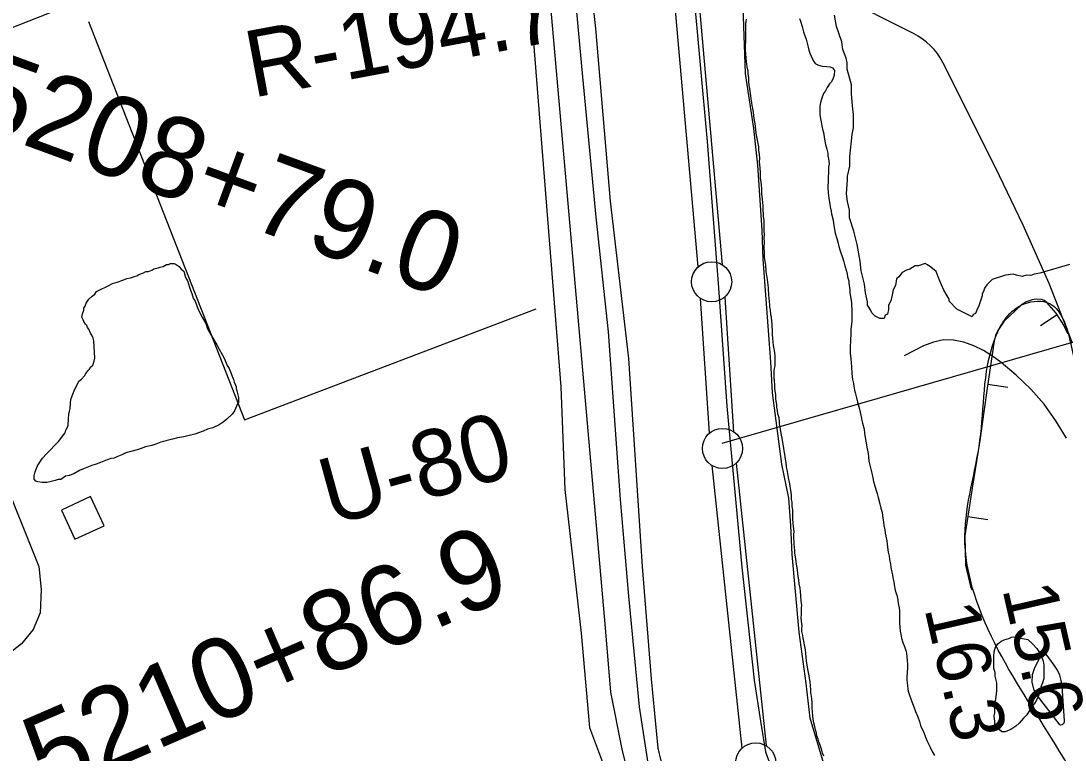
# Model space of a CAD drawing. Extents: x 3324125 to 3362000, y 600753 to 626151.
# Drawn here: x 3331428 to 3332729, y 615545 to 616457 of the extents above; entities that cross this region are included whole.
import ezdxf

# ---------------------------------------------------------------- set-up
doc = ezdxf.new("R2010")
doc.units = 0
for name, color, linetype in [('V-BLDG-OTLN', 7, 'Continuous'), ('V-BORW-LINE', 7, 'Continuous'), ('V-FLOD-BASE', 7, 'Continuous'), ('V-LEVE-TOET', 7, 'Continuous'), ('V-RIVR-RANG', 7, 'Continuous'), ('V-RIVR-RANG-IDEN', 7, 'Continuous'), ('V-ROAD-CNTR', 7, 'Continuous'), ('V-SITE-VEGE', 7, 'Continuous'), ('V-SURV-IDEN', 7, 'Continuous'), ('V-SURV-LINE', 7, 'Continuous'), ('V-TOPO-MAJR', 7, 'Continuous'), ('V-TOPO-MINR', 7, 'Continuous'), ('V-TOPO-SHOR', 7, 'Continuous')]:
    doc.layers.add(name, color=color, linetype=linetype)

msp = doc.modelspace()

# ---------------------------------------------------------------- linework, layer by layer
at = {"layer": 'V-BLDG-OTLN'}
msp.add_lwpolyline([(3331478.4, 615847.9), (3331495.3, 615811.6), (3331531.6, 615828.4), (3331514.7, 615864.7)], close=True, dxfattribs=at)
at = {"layer": 'V-BORW-LINE'}
for p, q in [((3332718.9, 616090.9), (3332697.8, 616077.5)), ((3332632.4, 616004.7), (3332657.2, 616001.1)), ((3332607.5, 615839.9), (3332632.2, 615836.1))]:
    msp.add_line(p, q, dxfattribs=at)
msp.add_lwpolyline([(3332731.9, 616067.4), (3332727.1, 616078.1), (3332717.6, 616093.1), (3332705.8, 616106.6), (3332702.6, 616108.9), (3332699.2, 616110.2), (3332692.8, 616110.7), (3332687.7, 616109.9), (3332680.3, 616107.2), (3332674, 616103), (3332652.7, 616083.1), (3332644.7, 616071.7), (3332642, 616065.5), (3332640.3, 616058.8), (3332631.3, 615996.6), (3332622.6, 615934.4), (3332612.9, 615875), (3332603.8, 615815.7), (3332604.4, 615779.4), (3332610.8, 615752.5), (3332612.4, 615748.3)], dxfattribs=at)
msp.add_spline([(3332917.4, 615371.8), (3332899, 615439.4), (3332887.3, 615494.3), (3332880.8, 615523.3), (3332845.9, 615674.6), (3332824, 615722.5), (3332777.6, 615836.6), (3332752.4, 615941.7), (3332736.3, 616052.4), (3332705.8, 616106.6), (3332674, 616103), (3332640.3, 616058.8), (3332622.6, 615934.4), (3332603.8, 615815.7), (3332645.4, 615673.5), (3332721.4, 615548), (3332760.5, 615451.5), (3332755.7, 615377.8), (3332775.8, 615229.9), (3332813.7, 615165), (3332893.3, 615037.2), (3332934.5, 614958.4), (3332934.6, 614916.2), (3332988.5, 614783.9), (3333008.6, 614752.7), (3333075.6, 614714.2), (3333096.8, 614723.6), (3333115.8, 614749.8), (3333132, 614783.4), (3333134.7, 614840.7), (3333127.6, 614881.8), (3333098, 614931.1), (3333018.3, 615080.4), (3332968.6, 615208.8), (3332941.7, 615292.2), (3332917.4, 615371.8)], degree=3, dxfattribs=at)
at = {"layer": 'V-FLOD-BASE'}
msp.add_lwpolyline([(3332227.4, 616947.5), (3332230.4, 616875.1), (3332240.2, 616761.9), (3332252.8, 616641.6), (3332265.3, 616498.5), (3332282.8, 616307), (3332296.8, 616124.8), (3332307.5, 615977.1), (3332326, 615776.8), (3332341.5, 615636.1), (3332349.3, 615584.7), (3332355.5, 615546.7), (3332369.2, 615509.3), (3332410.1, 615416.8), (3332454.9, 615312.6), (3332517, 615173.9)], dxfattribs=at)
at = {"layer": 'V-LEVE-TOET'}
for points in [[(3332098.6, 616972.3), (3332097, 616912.8), (3332109.7, 616793), (3332125.4, 616612.6), (3332143.6, 616447.9), (3332162.1, 616232.5), (3332184.7, 616036.8), (3332201.7, 615777.6), (3332213.1, 615637.5), (3332221.3, 615551.1), (3332240, 615472.2), (3332264.7, 615412.5), (3332328.7, 615293.6), (3332371.9, 615197.6)], [(3332428.3, 615531.7), (3332411.2, 615588.4), (3332406.2, 615631.6), (3332397.3, 615695.8), (3332388.5, 615792.6), (3332387.1, 615828.8), (3332384.4, 615862.8), (3332375.9, 615904.9), (3332364.3, 615994), (3332362, 616032.7), (3332352.6, 616160.4), (3332351.5, 616196.6), (3332346.1, 616277.4), (3332340.9, 616323), (3332330.7, 616391.5), (3332327.8, 616474.5), (3332325.5, 616507.5), (3332317.3, 616593.3), (3332302.9, 616718.9), (3332296.5, 616811.1), (3332286, 616894.6), (3332282.9, 616965.2)]]:
    msp.add_lwpolyline(points, dxfattribs=at)
at = {"layer": 'V-RIVR-RANG'}
msp.add_line((3332301.4, 615931.2), (3333589, 616302.4), dxfattribs=at)
at = {"layer": 'V-ROAD-CNTR'}
for points in [[(3332050.3, 616945.8), (3332056, 616867), (3332083.1, 616527.3), (3332155.9, 615701.2), (3332162.6, 615620.8), (3332176.4, 615550.1), (3332191.1, 615490.1), (3332204, 615447.5), (3332252.4, 615333.1), (3332828.6, 614063.2)], [(3332062.8, 616703.3), (3331299.1, 616402.5), (3331283.7, 616393.5), (3331269.2, 616382.1), (3331260.5, 616370.6), (3331252.7, 616347.9), (3331246.8, 616320), (3331249.3, 616296.2), (3331258.3, 616256.3), (3331450.3, 615777.5), (3331453.2, 615748.7), (3331451.9, 615720), (3331443.3, 615699.2), (3331428.9, 615681.4), (3331411.3, 615667.7), (3331394.3, 615658.1), (3330239.3, 615193.5), (3328629.8, 614542.4), (3328220.6, 614377)]]:
    msp.add_lwpolyline(points, dxfattribs=at)
at = {"layer": 'V-SITE-VEGE'}
for points in [[(3332734.1, 616153.6), (3332697, 616142.9), (3332690.1, 616141.6), (3332686, 616140.2), (3332680.5, 616140.3), (3332675, 616138.9), (3332668.1, 616140.4), (3332664, 616141.8), (3332654.4, 616140.4), (3332637.9, 616135.1), (3332631, 616128.3), (3332628.3, 616124.2), (3332626.9, 616120), (3332625.5, 616117.3), (3332625.4, 616114.6), (3332621.3, 616102.3), (3332618.5, 616096.8), (3332617.1, 616092.7), (3332614.3, 616091.3), (3332612.9, 616088.6), (3332602, 616094.1), (3332593.8, 616098.3), (3332584.3, 616108), (3332584.3, 616110.7), (3332581.6, 616114.9), (3332577.5, 616121.7), (3332574.8, 616128.6), (3332570.7, 616138.2), (3332568, 616145.1), (3332561.2, 616150.6), (3332557.1, 616153.4), (3332554.4, 616154.8), (3332546.1, 616152.1), (3332542, 616152.1), (3332535.1, 616148.1), (3332531, 616146.7), (3332525.5, 616144), (3332521.4, 616138.6), (3332518.6, 616135.8), (3332517.2, 616127.6), (3332514.4, 616122.1), (3332513, 616113.9), (3332511.6, 616108.4), (3332508.8, 616103), (3332508.7, 616097.5), (3332507.3, 616092), (3332504.6, 616090.7), (3332503.2, 616086.6), (3332500.4, 616086.6), (3332497.7, 616086.6), (3332492.2, 616089.4), (3332488.1, 616093.5), (3332486.8, 616096.3), (3332484.1, 616100.4), (3332482.7, 616103.1), (3332482.7, 616107.3), (3332480.1, 616118.3), (3332478.8, 616129.2), (3332474.8, 616145.7), (3332473.5, 616158.1), (3332469.5, 616178.7), (3332465.5, 616195.2), (3332460.1, 616211.7), (3332460.2, 616221.3), (3332457.5, 616232.2), (3332456.2, 616241.9), (3332457.7, 616259.7), (3332457.7, 616263.8), (3332460.5, 616276.1), (3332460.6, 616288.5), (3332463.5, 616315.9), (3332464.9, 616324.1), (3332465, 616340.6), (3332463.7, 616351.5), (3332462.5, 616366.6), (3332462.5, 616377.6), (3332457.2, 616396.9), (3332457.2, 616405.1), (3332455.9, 616410.6), (3332451.9, 616421.6), (3332450.5, 616431.2), (3332443.8, 616450.4), (3332441.2, 616464.2)], [(3331583.2, 615926.8), (3331577.6, 615924.5), (3331572.8, 615922.9), (3331564.9, 615920.6), (3331558.5, 615919), (3331553.7, 615916.7), (3331547.3, 615914.3), (3331544.1, 615912.7), (3331540.1, 615912), (3331535.3, 615910.4), (3331527.3, 615907.3), (3331521.7, 615904.9), (3331516.2, 615903.3), (3331505.8, 615899.4), (3331501, 615897.1), (3331493.8, 615893.1), (3331488.2, 615890.8), (3331483.4, 615890), (3331477.8, 615886.1), (3331474.6, 615886.1), (3331470.6, 615884.5), (3331464.2, 615883), (3331460.3, 615882.2), (3331454.7, 615882.2), (3331449.1, 615883.1), (3331446.7, 615883.9), (3331444.4, 615886.3), (3331444.4, 615890.3), (3331445.2, 615894.3), (3331448.4, 615902.2), (3331451.7, 615907.7), (3331454.9, 615912.5), (3331459.7, 615918.1), (3331474.9, 615933.1), (3331481.4, 615941.8), (3331483, 615944.2), (3331483.8, 615947.4), (3331486.2, 615951.3), (3331487, 615953.7), (3331487.1, 615961.7), (3331487.9, 615967.3), (3331488.7, 615971.2), (3331489.5, 615974.4), (3331489.6, 615981.6), (3331490.4, 615985.6), (3331492, 615990.3), (3331495.3, 615998.3), (3331498.5, 616004.6), (3331500.1, 616008.6), (3331503.3, 616011), (3331507.3, 616014.9), (3331508.9, 616018.1), (3331511.3, 616021.3), (3331512.9, 616022.9), (3331514.6, 616026), (3331517.8, 616028.4), (3331519.4, 616033.2), (3331520.2, 616037.1), (3331518.8, 616058.7), (3331518, 616061.8), (3331516.4, 616065.8), (3331514.8, 616068.2), (3331512.5, 616073), (3331510.9, 616075.4), (3331510.1, 616077.8), (3331508.5, 616079.4), (3331506.2, 616082.6), (3331505.4, 616085), (3331503.8, 616088.2), (3331504.6, 616092.2), (3331506.3, 616097), (3331506.3, 616099.4), (3331507.9, 616101.7), (3331509.5, 616105.7), (3331512.7, 616110.5), (3331516.7, 616114.4), (3331519.9, 616116.8), (3331522.3, 616120), (3331527.9, 616123.1), (3331533.5, 616125.5), (3331537.5, 616127.8), (3331542.3, 616130.2), (3331547.9, 616131.7), (3331555.1, 616134.1), (3331559.9, 616136.5), (3331564.7, 616137.2), (3331569.4, 616138.8), (3331572.6, 616139.6), (3331575, 616141.1), (3331580.6, 616143.5), (3331583.8, 616145.1), (3331587, 616145), (3331591, 616146.6), (3331593.4, 616148.2), (3331599, 616149.7), (3331601.4, 616150.5), (3331605.4, 616151.3), (3331609.4, 616153.7), (3331611.8, 616153.6), (3331614.2, 616155.2), (3331618.9, 616155.2)], [(3331618.9, 616155.2), (3331621.3, 616153.6), (3331625.3, 616151.2), (3331627.7, 616148), (3331630.8, 616145.6), (3331633.2, 616137.6), (3331635.5, 616133.6), (3331639.4, 616121.6), (3331641, 616117.6), (3331642.6, 616112), (3331644.9, 616108), (3331648.8, 616097.6), (3331653.6, 616088.1), (3331658.3, 616080.1), (3331660.6, 616073.7), (3331672.4, 616052.9), (3331674.8, 616048.1), (3331678.7, 616041.7), (3331681.1, 616036.9), (3331682.7, 616032.9), (3331685, 616028.1), (3331687.4, 616024.1), (3331692.9, 616010.5), (3331693.7, 616007.3), (3331696, 616001.8), (3331696, 615999.4), (3331696.8, 615996.2), (3331698.3, 615991.4), (3331699.1, 615988.2), (3331699.1, 615981.8), (3331697.5, 615979.4), (3331696.6, 615977.1), (3331694.2, 615971.5), (3331691, 615967.5), (3331684.6, 615961.2), (3331679.8, 615957.3), (3331675, 615954.1), (3331667, 615950.2), (3331660.6, 615948.6), (3331655, 615946.3), (3331644.6, 615942.3), (3331637.5, 615940.8), (3331631.1, 615939.2), (3331623.1, 615937.7), (3331616.7, 615936.2), (3331602.4, 615932.3), (3331596, 615929.9), (3331591.2, 615928.4), (3331583.2, 615926.8)]]:
    msp.add_lwpolyline(points, dxfattribs=at)
at = {"layer": 'V-SURV-LINE'}
for points in [[(3332271.7, 616150.7), (3332204.2, 616912.5)], [(3332234.1, 616915.1), (3332301.6, 616153.4)], [(3332285.6, 615943.6), (3332274.7, 616111.3)], [(3332304.7, 616113.2), (3332315.5, 615945.5)], [(3332326.3, 615551.2), (3332289, 615903.2)], [(3332318.9, 615906.3), (3332356.1, 615554.4)]]:
    msp.add_lwpolyline(points, dxfattribs=at)
for centre in [(3332288.4, 616132.2), (3332301.9, 615924.6), (3332343.3, 615532.9)]:
    msp.add_circle(centre, 25, dxfattribs=at)
at = {"layer": 'V-TOPO-MAJR'}
msp.add_lwpolyline([(3332738, 616055.9), (3332708.7, 616129.9), (3332676.5, 616202.7), (3332642.1, 616274.7), (3332576.3, 616405.6), (3332573.1, 616411.2), (3332569.5, 616416.6), (3332565.5, 616421.6), (3332561, 616426.3), (3332556.2, 616430.6), (3332551.1, 616434.6), (3332545.7, 616438.2), (3332540, 616441.4), (3332445.4, 616489.4), (3332444.4, 616489.8), (3332442.3, 616490.2), (3332438.9, 616489.9)], dxfattribs=at)
at = {"layer": 'V-TOPO-MINR'}
for points in [[(3332730.3, 615937.3), (3332717.3, 615959.1), (3332702.7, 615979.7), (3332685.9, 615998.4), (3332667.5, 616016), (3332649.1, 616031.6), (3332638.4, 616039.6), (3332627.1, 616046.7), (3332615, 616052.4), (3332602.5, 616057.2), (3332589.6, 616059.5), (3332577, 616059.9), (3332564.6, 616057.2), (3332552.4, 616052.6), (3332528.3, 616040)], [(3332700.5, 615669.6), (3332699.9, 615669.2), (3332699.4, 615668.5), (3332690.6, 615651.5), (3332687.8, 615642.4), (3332687.1, 615633.5), (3332689.4, 615624.8), (3332693.8, 615616.4), (3332721, 615581.4), (3332723.1, 615580.1), (3332725.5, 615580.6), (3332727.4, 615582.7), (3332727.8, 615583.9), (3332727.9, 615585.4), (3332725, 615628.3), (3332723.9, 615635.4), (3332722, 615642.1), (3332719, 615648.4), (3332715.2, 615654.5), (3332704.9, 615668.3), (3332703.6, 615669.4), (3332702, 615669.9), (3332700.5, 615669.6)]]:
    msp.add_lwpolyline(points, dxfattribs=at)
at = {"layer": 'V-TOPO-SHOR'}
for points in [[(3332079.8, 617015.2), (3332079.2, 616924), (3332083.6, 616853.8), (3332095.6, 616737.5), (3332102.8, 616629.9), (3332115.3, 616517.9), (3332127.6, 616387.6), (3332144.3, 616212.6), (3332159.4, 616070), (3332174.3, 615861.2), (3332184.7, 615740.4), (3332198.2, 615602.9), (3332211.5, 615516.4), (3332226.3, 615457), (3332245.5, 615405.9), (3332276.9, 615338.4), (3332310.8, 615281.2), (3332354.3, 615179.4)], [(3332049.3, 616645.5), (3332100.4, 616001.2), (3332105.5, 615873.4), (3332126, 615694.4), (3332136.2, 615576.8), (3332182.2, 615454.1), (3332264.1, 615239.3), (3332483.9, 614768.9), (3332673.1, 614344.5), (3332708.9, 614267.7)], [(3331512.4, 616456.3), (3331706.7, 615960.3), (3332069.7, 616098.4)], [(3332363.9, 616076.5), (3332363.6, 616079.7), (3332363.2, 616082.8), (3332362.8, 616088), (3332362, 616091.2), (3332361.7, 616097.2), (3332360.9, 616100.4), (3332360.9, 616104), (3332360.6, 616107.1), (3332360.2, 616112.3), (3332359.8, 616115.5), (3332359.1, 616124.3), (3332358.7, 616128.3), (3332358, 616135), (3332357.2, 616140.2), (3332356.4, 616145), (3332355.7, 616153), (3332354.9, 616157.8), (3332354.1, 616162.5), (3332354.2, 616169.3), (3332353.8, 616174.1), (3332354.3, 616181.7), (3332353.9, 616186.4), (3332354.3, 616191.2), (3332354, 616195.6), (3332354, 616201.2), (3332353.6, 616205.2), (3332353.6, 616208.4), (3332352.9, 616213.9), (3332352.9, 616217.5), (3332352.5, 616221.1), (3332352.6, 616226.7), (3332352.2, 616231.1), (3332351.8, 616235), (3332351.1, 616242.2), (3332351.1, 616247.4), (3332350.4, 616253.4), (3332349.2, 616262.1), (3332349.3, 616268.1), (3332348.9, 616274.1), (3332348.1, 616281.7), (3332348.2, 616286.4), (3332347.8, 616290.8), (3332347, 616296.4), (3332347.1, 616300.4), (3332345.9, 616306.4), (3332345.1, 616310.8), (3332344.4, 616314.8), (3332343.6, 616321.1), (3332342.9, 616325.5), (3332342.5, 616329.5), (3332341.3, 616335.5), (3332341, 616339.5), (3332340.6, 616343.1), (3332339.8, 616348.6), (3332339, 616351.8), (3332338.3, 616355), (3332337.5, 616360.6), (3332337.1, 616363.8), (3332336, 616373), (3332335.2, 616376.9), (3332334.8, 616381.3), (3332334.5, 616386.9), (3332333.7, 616390.9), (3332333.7, 616394.5), (3332332.6, 616400.1), (3332332.2, 616403.2), (3332331.8, 616406.4), (3332331.5, 616410.8), (3332331.1, 616416.4), (3332330.7, 616421.2), (3332330.7, 616424.8), (3332330.8, 616433.1), (3332330.8, 616437.5), (3332330.9, 616443.9), (3332330.9, 616448.7), (3332330.9, 616453.4), (3332331.8, 616459.4)], [(3332397.9, 616460.2), (3332399.1, 616457), (3332401, 616450.2), (3332401.8, 616447), (3332403, 616443.8), (3332404.1, 616439.8), (3332406.1, 616434.6), (3332407.2, 616429.4), (3332408.8, 616424.7), (3332409.6, 616420.7), (3332410.8, 616417.1), (3332412.3, 616413.5), (3332413.9, 616409.5), (3332415.5, 616406.7), (3332417.4, 616404.3), (3332421.4, 616401.9), (3332426.2, 616401), (3332431.4, 616400.6), (3332436.1, 616399.8), (3332438.9, 616398.6), (3332441.3, 616395.4), (3332440.8, 616389.8), (3332439.2, 616384.6), (3332437.2, 616381.1), (3332435.2, 616378.7), (3332432.4, 616374.3), (3332430, 616370), (3332427.9, 616366.8), (3332425.9, 616362.4), (3332424.3, 616357.2), (3332423.1, 616350.9), (3332423, 616347.7), (3332423, 616340.5), (3332423.8, 616335.3), (3332424.9, 616331.4), (3332425.7, 616326.6), (3332426.5, 616322.2), (3332427.6, 616318.2), (3332428.4, 616313), (3332429.2, 616307.4), (3332430.3, 616303.4), (3332431.9, 616297.5), (3332433, 616292.3), (3332433, 616289.1), (3332433.8, 616285.5), (3332434.6, 616279.1), (3332434.1, 616275.1), (3332434.1, 616268.4), (3332433.7, 616262.8), (3332433.6, 616258)], [(3332433.6, 616258), (3332433.2, 616250.1), (3332433.5, 616242.5), (3332434.7, 616233.3), (3332435.4, 616228.9), (3332436.2, 616225.7), (3332437.4, 616220.2), (3332437.7, 616217), (3332439.7, 616209), (3332440.1, 616205.4), (3332441.6, 616197.4), (3332442.4, 616193), (3332444.3, 616186.3), (3332445.5, 616181.5), (3332447, 616176.3), (3332448.6, 616170.7), (3332451.3, 616162.3), (3332452.9, 616157.1), (3332454.4, 616152.3), (3332456.4, 616145.6), (3332457.2, 616141.6), (3332457.5, 616138.4), (3332459.1, 616133.6), (3332459.1, 616130.4), (3332460.6, 616122), (3332460.6, 616118.5), (3332461.7, 616111.3), (3332462.5, 616106.1), (3332462.8, 616094.9), (3332462.8, 616089), (3332462.8, 616082.6), (3332461.9, 616073.4), (3332461.9, 616067.1), (3332461.4, 616059.9), (3332461, 616049.9), (3332460.9, 616043.2), (3332461.7, 616036.4), (3332462.4, 616026.4), (3332463.1, 616018.1), (3332463.9, 616010.5), (3332465, 616005.7), (3332465.4, 616002.1), (3332466.2, 615997.3), (3332467, 615994.2), (3332468.9, 615987.8), (3332470.1, 615982.2), (3332471.6, 615976.6), (3332472.4, 615973.4), (3332473.2, 615969.8), (3332474.7, 615963.8), (3332475.5, 615959.4), (3332476.3, 615955.9), (3332478.2, 615948.7), (3332478.6, 615943.5), (3332480.1, 615935.9), (3332480.9, 615931.5), (3332481.7, 615926.4), (3332483.2, 615918.4), (3332483.6, 615914), (3332484.3, 615908.8), (3332485.9, 615902), (3332487, 615897.2), (3332487.8, 615893.7), (3332489, 615888.1), (3332490.1, 615883.3), (3332491.3, 615879.3), (3332493.3, 615872.1), (3332494.4, 615868.5), (3332496, 615863.3), (3332497.9, 615855.8), (3332499.1, 615850.2), (3332500.6, 615845), (3332501.8, 615837.8), (3332502.6, 615833), (3332502.9, 615828.6), (3332504.1, 615823.1), (3332504.5, 615819.1), (3332505.2, 615815.5), (3332506.4, 615809.5), (3332506.8, 615805.5), (3332507.5, 615801.5), (3332508.3, 615795.2), (3332509.5, 615790.4), (3332509.8, 615786.4), (3332511, 615780.4), (3332511.4, 615776.4), (3332512.9, 615770.4), (3332513.7, 615767.2), (3332514.1, 615763.3), (3332515.2, 615758.5), (3332515.6, 615754.5), (3332517.1, 615748.1), (3332518.3, 615744.1), (3332519.5, 615740.5), (3332520.3, 615735.3), (3332520.6, 615731.3), (3332521.8, 615726.2), (3332522.2, 615722.2), (3332522.5, 615717.4), (3332522.5, 615712.2), (3332522.5, 615707.4)], [(3332411.6, 615628.5), (3332410.9, 615634.1), (3332410.1, 615638.1), (3332409.7, 615641.3), (3332408.6, 615647.6), (3332407.4, 615654.8), (3332406.7, 615660), (3332406.3, 615664), (3332405.5, 615669.6), (3332405.2, 615673.6), (3332404, 615679.9), (3332403.2, 615684.7), (3332402.5, 615688.3), (3332402.1, 615691.5), (3332400.9, 615696.7), (3332400.9, 615700.3), (3332401, 615703.8), (3332400.2, 615709.4), (3332399.8, 615713.8), (3332400.3, 615717.4), (3332400.3, 615722.6), (3332400.3, 615726.2), (3332400.7, 615729.3), (3332400, 615734.5), (3332399.6, 615740.9), (3332398.9, 615746.5), (3332398.5, 615750.5), (3332397.3, 615756), (3332397, 615760.8), (3332396.2, 615765.2), (3332395.8, 615768.8), (3332395.4, 615773.2), (3332395.1, 615776.4), (3332393.9, 615780.4), (3332393.5, 615783.9), (3332392.8, 615789.5), (3332392, 615794.3), (3332392, 615797.5), (3332391.3, 615805.9), (3332391.3, 615809), (3332390.9, 615812.6), (3332390.9, 615817.4), (3332391, 615821), (3332390.6, 615824.2), (3332390.2, 615827.8), (3332389.8, 615831), (3332389.5, 615837.3), (3332389.5, 615843.7), (3332389.6, 615848.1), (3332388.8, 615852.1), (3332388.8, 615857.7), (3332388, 615861.2), (3332387.7, 615866.4), (3332387.3, 615870), (3332386.5, 615874.8), (3332386.2, 615878), (3332385.4, 615882.4), (3332384.6, 615886), (3332383.9, 615890.7), (3332382.7, 615895.9), (3332381.5, 615901.9), (3332381.2, 615907.1), (3332380.4, 615911.1), (3332379.6, 615917.5), (3332378.9, 615921.8), (3332378.1, 615925), (3332377, 615932.2), (3332376.2, 615937.4), (3332375.4, 615941), (3332374.7, 615945.8), (3332373.9, 615951.7), (3332373.1, 615954.9), (3332373.1, 615958.1), (3332372.4, 615962.9), (3332370.8, 615967.7), (3332370.4, 615971.7), (3332369.7, 615976.1), (3332369.7, 615979.2), (3332368.9, 615983.6), (3332368.5, 615986.8), (3332368.2, 615992), (3332367.4, 615996), (3332367, 615999.6), (3332367.1, 616003.6), (3332366.7, 616009.1), (3332366.3, 616013.1), (3332366.3, 616016.7), (3332366.4, 616021.1), (3332366.8, 616024.3), (3332367.6, 616027.5), (3332367.6, 616030.6), (3332367.3, 616036.2), (3332367.3, 616039.4), (3332366.9, 616044.2), (3332366.2, 616048.6), (3332365.4, 616053), (3332365, 616056.9), (3332364.6, 616062.1), (3332364.3, 616066.5), (3332364.3, 616072.1), (3332363.9, 616076.5)], [(3332522.5, 615707.4), (3332522.8, 615701.9), (3332523.2, 615697.1), (3332524, 615693.1), (3332524.7, 615688.3), (3332526.7, 615682.7), (3332528.6, 615677.9), (3332530.2, 615673.1), (3332531, 615669.6), (3332532.1, 615660.4), (3332532.5, 615656), (3332532.5, 615652), (3332532, 615645.2), (3332531.6, 615640.5), (3332531.6, 615636.1), (3332532.3, 615629.3), (3332532.7, 615625.3), (3332533.1, 615622.1), (3332535, 615617.4), (3332537, 615611.4), (3332538.5, 615607), (3332540.1, 615602.6), (3332542.1, 615597), (3332545.2, 615590.2), (3332547.2, 615584.6), (3332548.7, 615579.4), (3332552.6, 615570.6), (3332554.6, 615565.1), (3332557, 615559.9), (3332560.5, 615552.3), (3332563.2, 615547.1), (3332566, 615541.9)], [(3332682.4, 615686.8), (3332687.9, 615681.1), (3332693.5, 615675.5), (3332699, 615667.5), (3332699.8, 615664.3), (3332701.3, 615659.5), (3332702.1, 615654.8), (3332702.1, 615650), (3332702, 615645.2), (3332702, 615638), (3332700.4, 615632.5), (3332698.7, 615628.5), (3332697.1, 615622.1), (3332695.5, 615616.6), (3332693, 615611), (3332690.6, 615607), (3332688.2, 615603.9), (3332683.4, 615596.7), (3332681, 615592.8), (3332677, 615588.8), (3332671.4, 615582.5), (3332667.3, 615578.5), (3332660.9, 615574.6), (3332657, 615573), (3332653.8, 615571.4), (3332649.8, 615571.5), (3332643.4, 615577.1), (3332641.1, 615580.3), (3332641.1, 615584.3), (3332640.3, 615591.4), (3332641.2, 615595.4), (3332641.2, 615600.2), (3332641.2, 615606.6), (3332642.1, 615610.5), (3332642.9, 615615.3), (3332643.7, 615622.5), (3332643.8, 615627.3), (3332643.8, 615632.8), (3332641.5, 615640.8), (3332641.5, 615645.6), (3332639.9, 615650.4), (3332640, 615657.6), (3332640, 615662.3), (3332640, 615665.5), (3332640.1, 615671.1), (3332641.7, 615675.9), (3332644.9, 615681.4), (3332648.9, 615684.6), (3332652.9, 615686.1), (3332658.5, 615687.7), (3332661.7, 615689.3), (3332664.9, 615690.1), (3332668.9, 615689.2), (3332682.4, 615686.8)], [(3332428.2, 615541.2), (3332426.6, 615545.2), (3332425.5, 615548.8), (3332423.9, 615553.9), (3332421.9, 615559.1), (3332421.2, 615562.3), (3332419.6, 615566.7), (3332418.8, 615569.9), (3332417.7, 615573.9), (3332416.9, 615578.3), (3332415.7, 615582.7), (3332415, 615587.5), (3332414.6, 615591), (3332413.8, 615597), (3332413.4, 615601), (3332413.5, 615604.6), (3332413.5, 615607.8), (3332413.1, 615613), (3332412, 615620.5), (3332412, 615624.5), (3332411.6, 615628.5)]]:
    msp.add_lwpolyline(points, dxfattribs=at)

# ---------------------------------------------------------------- texts
at = {"layer": 'V-RIVR-RANG'}
for s, p in [('15.6', (3332650.2, 615749.6)), ('16.3', (3332553.2, 615725.3))]:
    msp.add_text(s, height=67, rotation=282.8783, dxfattribs=at).set_placement(p)
at = {"layer": 'V-RIVR-RANG-IDEN'}
for s, rotation, p in [('R-194.7', 10.6106, (3331716.5, 616361.3)), ('U-80', 15.3801, (3331813.9, 615828.2))]:
    msp.add_text(s, height=83, rotation=rotation, dxfattribs=at).set_placement(p)
at = {"layer": 'V-SURV-IDEN'}
for s, rotation, p in [('5208+79.0', 339.8878, (3331357, 616330.2)), ('5210+86.9', 23.3725, (3331460, 615489.7))]:
    msp.add_text(s, height=100, rotation=rotation, dxfattribs=at).set_placement(p)

doc.saveas('drawing.dxf')
